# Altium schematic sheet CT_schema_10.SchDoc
size 277 x 170 mm
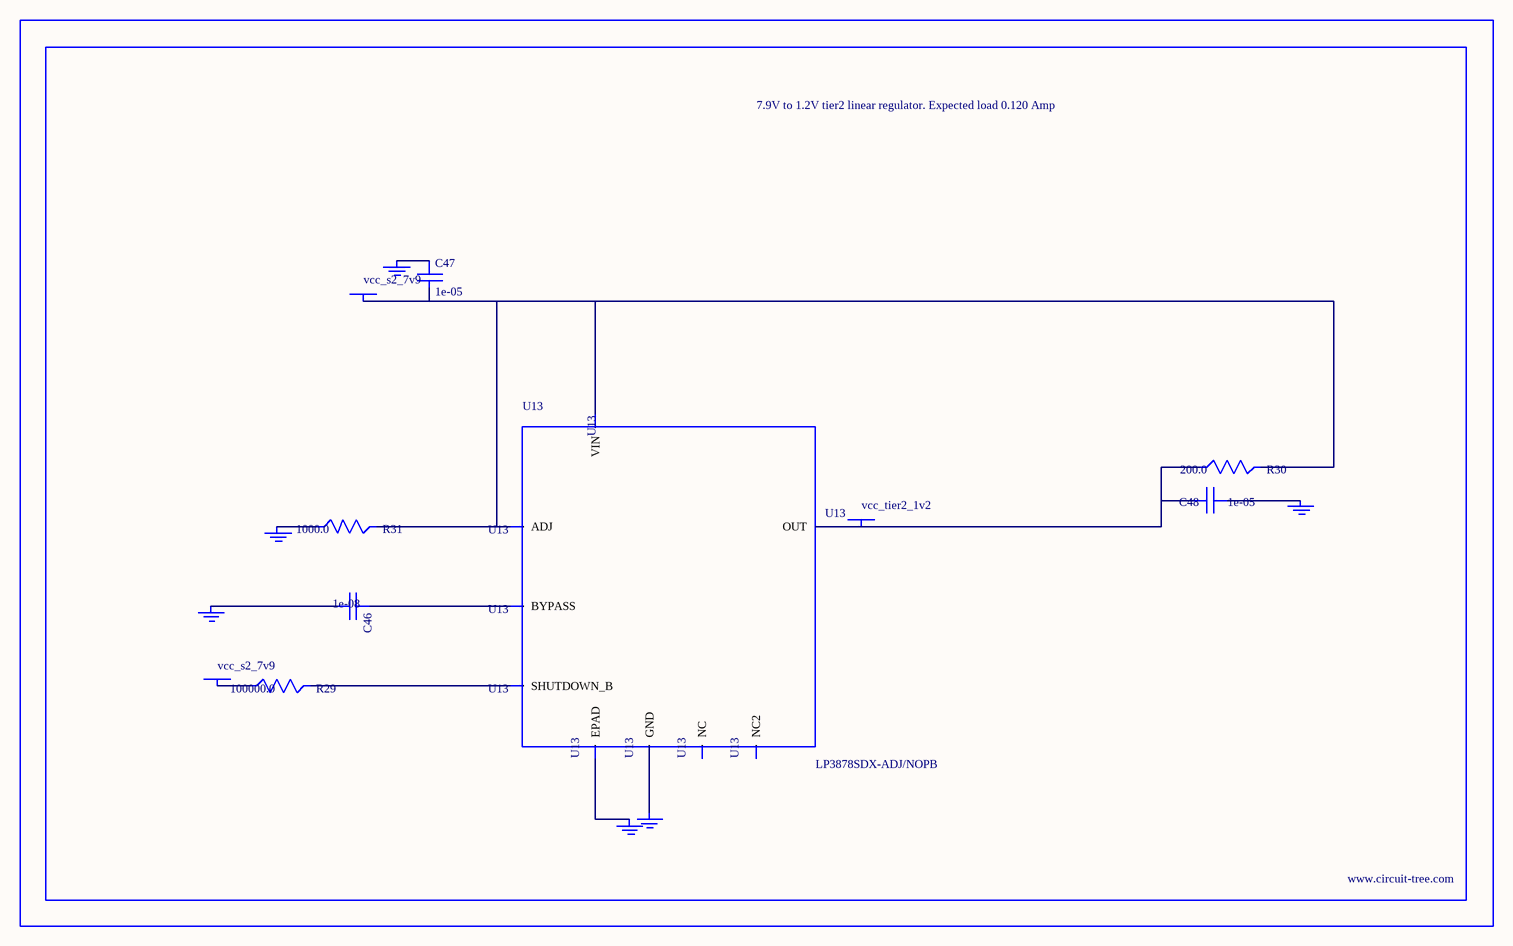
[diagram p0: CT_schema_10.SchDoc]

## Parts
BORDER9  (no value)
C46  1e-08  [C0402]
C47  1e-05  [C1206]
C48  1e-05  [C0805]
GND_INSTANCE_9_0  (no value)
GND_INSTANCE_9_1  (no value)
GND_INSTANCE_9_2  (no value)
GND_INSTANCE_9_3  (no value)
GND_INSTANCE_9_4  (no value)
GND_INSTANCE_9_5  (no value)
POWER_INSTANCE_9_0  vcc_s2_7v9
POWER_INSTANCE_9_1  vcc_s2_7v9
POWER_INSTANCE_9_2  vcc_tier2_1v2
R29  100000.0  [R0603]
R30  200.0  [R0603]
R31  1000.0  [R0603]
U13  LP3878SDX-ADJ/NOPB  [WSON-8]

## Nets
NetC46_1: C46.1 U13.1(BYPASS)
NetC46_2: C46.2 GND_INSTANCE_9_0.0(GND)
NetC47_1: C47.1 GND_INSTANCE_9_1.0(GND)
NetC47_2: C47.2 POWER_INSTANCE_9_0.0(PWR) R30.2 R31.2 U13.4(VIN) U13.6(ADJ)
NetC48_1: C48.1 GND_INSTANCE_9_2.0(GND)
NetC48_2: C48.2 POWER_INSTANCE_9_2.0(PWR) R30.1 U13.5(OUT)
NetGND_INSTANCE_9_3_0: GND_INSTANCE_9_3.0(GND) R31.1
NetGND_INSTANCE_9_4_0: GND_INSTANCE_9_4.0(GND) U13.PAD(EPAD)
NetGND_INSTANCE_9_5_0: GND_INSTANCE_9_5.0(GND) U13.3(GND)
NetPOWER_INSTANCE_9_1_0: POWER_INSTANCE_9_1.0(PWR) R29.1
NetR29_2: R29.2 U13.8(SHUTDOWN_B)

Not connected (* = marked no-connect by the designer): U13 2(NC) 7(NC2)

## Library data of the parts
BORDER9 = BORDER_PAGE9
C46 = C0402C103K3RAC
C47 = C1206C106K3RACTU
C48 = GRM219R60J106ME19D
GND_INSTANCE_9_0-GND_INSTANCE_9_5 = GND
POWER_INSTANCE_9_0-POWER_INSTANCE_9_2 = PWR
R29 = RC0603JR-07100KL
R30 = RC0603JR-07200RL
R31 = RC0603JR-071KL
